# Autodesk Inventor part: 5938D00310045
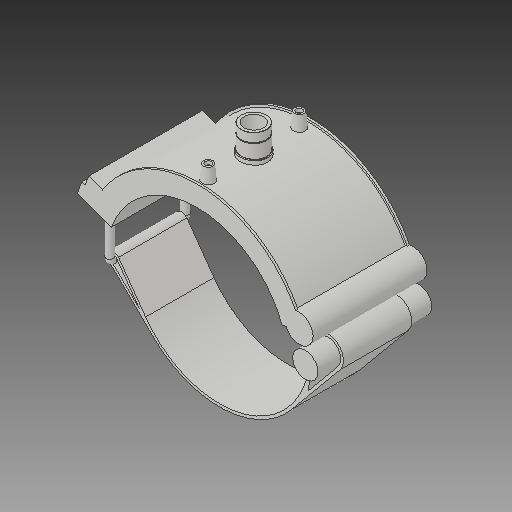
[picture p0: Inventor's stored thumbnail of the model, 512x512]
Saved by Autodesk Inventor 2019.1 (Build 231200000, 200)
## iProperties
Created: 2017-07
Part Number: 5938D00310045
Material: Generic
Description: PLASSON TRANSITION SADDLE 10''DIPS x 1"NPT
Document SubType Name: Modeling
Designer: KIM
Density: 1 g/cm^3
Appearance: Default
Author: KIM
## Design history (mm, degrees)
derived "5938D.ipt"
feature "Solid1::5938D.ipt"
tag "TaggingFeature1"
body "Solid1"
other parameters: "d0" = 280.6, "d1" = 336.72, "d2" = 450.85, "d3" = 70.15, "d4" = 176.022, "d5" = 0, "d40" = 175.0944, "d41" = 42.4074, "d43" = 0, "d45" = 0, "d47" = 210.27, "d48" = 39.3783, "d50" = 0, "d78" = 190.36, "d79" = 15, "d80" = 70.4088, "d82" = 5 deg, "d84" = 4, "d85" = 14, "d86" = 0, "d87" = 3, "d88" = 0, "d96" = 343.4544, "d97" = 3.52044, "d98" = 0, "d102" = 0.90873, "d103" = 30.291, "d104" = 25.146, "d105" = 0, "d106" = 24.2328, "d108" = 0, "d109" = -13.97, "d111" = 0.5, "d112" = 0.5, "d113" = 0, "d114" = 0.5, "d117" = 0.30291, "d120" = 140 deg, "d121" = 24.228, "d122" = 20 deg, "d123" = 1346.88, "d124" = 202.032, "d126" = 0, "d143" = 289.018, "d145" = 43.16923, "d149" = 4.209, "d150" = 47.48615, "d153" = 176.022, "d154" = 0, "d156" = 168.36, "d157" = 160 deg, "d159" = 11.224, "d161" = 4.209, "d162" = 105.6132, "d163" = 0, "d164" = 140.3, "d167" = 28.06, "d168" = 164.25366, "d170" = 4.209, "d172" = 0, "d173" = 1, "d175" = 140.3, "d176" = 20 deg, "d177" = 19.642, "d178" = 56.12, "d180" = 0, "d183" = 22.448, "d184" = 15.7136, "d185" = 57.20715, "d186" = 57.20715, "d187" = 168.36, "d188" = 16.836, "d189" = 19.642, "d190" = 0, "d191" = 202.032, "d193" = 11.224, "d194" = 5.7523, "d195" = 90 deg, "d197" = 0, "d199" = 0, "d_" = 280.6, "B_" = 180.34, "H_" = 41.91, "L_" = 176.022, "d_t" = 6, "G_" = 30.291, "d148" = 4.209, "d160" = 4.209, "d169" = 4.209, "d192" = 11.224
